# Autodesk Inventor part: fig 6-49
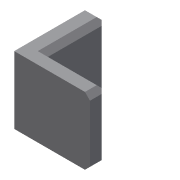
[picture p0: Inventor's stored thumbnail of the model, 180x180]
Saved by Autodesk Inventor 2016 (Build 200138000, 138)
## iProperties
Created: 2009-09
Part Number: fig 6-49
Document SubType Name: Modeling
Designer: Sham
Density: 1 g/cm^3
Material: Generic
Appearance: Default
Author: Sham
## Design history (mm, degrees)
sketch "Sketch1"
  geometry: L1 (1.789, 30)-(1.789, -5); L2 (1.789, -5)-(36.789, -5); L3 (36.789, -5)-(36.789, -15); L4 (36.789, -15)-(-8.211, -15); L5 (-8.211, -15)-(-8.211, 30); L6 (-8.211, 30)-(1.789, 30)
  constraints: 12 end point, 6 perpendicular
  dimensions: "d0" = 10 distance of L5.end L1.start; "d1" = 35 distance of L1.start L1.end; "d2" = 45 distance of L3.end L4.end; "d3" = 10 distance of L2.end L3.end (derived)
extrude "Extrusion1" new body sketch "Sketch1" distance "d4" = 40; taper "d5" = 0 deg
chamfer "Chamfer1" distance "d6" = 3; stored, may be unused: second distance "d7" = 2, angle "d8" = 45 deg
body "Solid1"
other parameters: "d1" = 35
